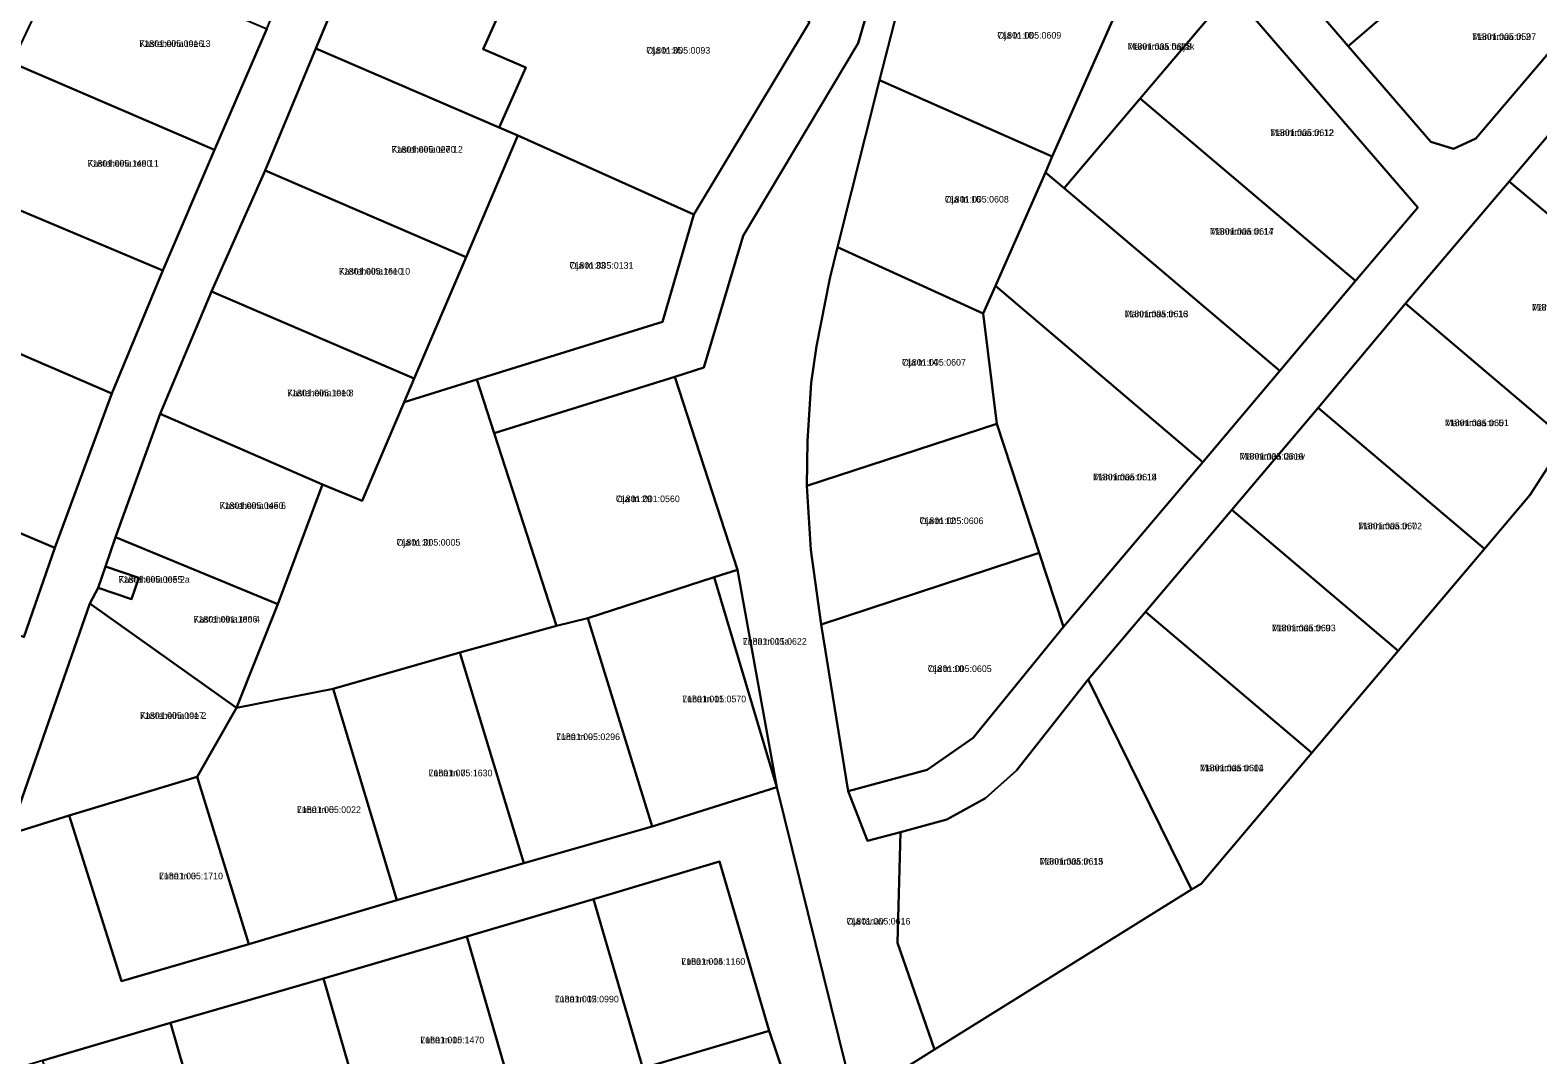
# Model space of a CAD drawing. Extents: x 529768 to 552006, y 6562269 to 6580975.
# Drawn here: x 536849.5 to 537191.7, y 6574124 to 6574356.4 of the extents above; entities that cross this region are included whole.
import ezdxf

# ---------------------------------------------------------------- set-up
doc = ezdxf.new("R2010")
doc.units = 0
for name, color, linetype in [('L_AADRESS', 7, 'Continuous'), ('PIIR', 7, 'Continuous'), ('TUNNUS', 7, 'Continuous')]:
    doc.layers.add(name, color=color, linetype=linetype)

msp = doc.modelspace()

# ---------------------------------------------------------------- linework, layer by layer
at = {"layer": 'PIIR'}
for points in [[(536848.11, 6574218.76), (536855.09, 6574238.97), (536868.03, 6574273.98), (536879.6, 6574301.9), (536891.37, 6574329.26), (536903.26, 6574356.78), (536914.89, 6574384.31), (536926.66, 6574411.99), (536938.46, 6574439.65), (536950.24, 6574467.12), (536913.03, 6574482.78), (536876.66, 6574498.44), (536839.93, 6574514.2)], [(537058.85, 6574426.74), (537037.46, 6574353.46), (537011.36, 6574309.79), (537002.42, 6574279.87), (536995.85, 6574277.77), (536954.81, 6574265.02), (536950.86, 6574277.19), (536993.03, 6574290.28), (537000.17, 6574314.62), (537026.37, 6574358.24)], [(537051.59, 6574381.3), (537042.29, 6574345.06), (537032.75, 6574307.23), (537030.98, 6574300.09), (537027.97, 6574284.72), (537026.74, 6574276.42), (537025.95, 6574263.3), (537025.82, 6574253.03), (537026.7, 6574238.56), (537029.01, 6574221.62), (537035.19, 6574183.8), (537039.58, 6574172.51), (537047.04, 6574174.52), (537046.35, 6574149.38), (537054.78, 6574125.16), (537036.51, 6574113.77), (537018.95, 6574184.72), (537010.08, 6574234.01), (536995.85, 6574277.77), (537002.42, 6574279.87), (537011.36, 6574309.79), (537037.46, 6574353.46), (537058.85, 6574426.74)], [(536925.81, 6574379.67), (536914.39, 6574352.3), (536902.87, 6574324.61), (536890.71, 6574297.13), (536879.02, 6574269.41), (536868.91, 6574241.43), (536866.6, 6574234.77), (536864.98, 6574229.95), (536863.06, 6574226.35), (536844.85, 6574174.03), (536858.39, 6574178.29), (536870.25, 6574140.65), (536899.17, 6574149.08), (536932.73, 6574159.05), (536961.59, 6574167.42), (536990.71, 6574175.75), (537018.95, 6574184.72), (537036.51, 6574113.77)], [(537128.66, 6574376.07), (537148.66, 6574352.81), (537167.43, 6574331.07), (537172.56, 6574329.53), (537177.64, 6574331.83), (537204.91, 6574363.99)], [(537212.84, 6574354.8), (537185.18, 6574322.09), (537161.63, 6574294.39), (537141.8, 6574270.76), (537122.23, 6574247.61), (537102.65, 6574224.46), (537089.61, 6574209.09), (537073.36, 6574188.47), (537066.32, 6574182.19), (537057.54, 6574177.35), (537047.04, 6574174.52), (537039.58, 6574172.51), (537035.19, 6574183.8), (537053.07, 6574188.61), (537063.54, 6574195.92), (537084.02, 6574221.05), (537115.69, 6574258.46), (537133.15, 6574279.15), (537150.3, 6574299.57), (537164.41, 6574316.2), (537122.1, 6574365.31)], [(537199.14, 6573885.6), (537082.16, 6574038.28), (537054.19, 6574078.17), (537036.51, 6574113.77), (537054.78, 6574125.16), (537113.11, 6574161.48), (537115.27, 6574162.8), (537140.4, 6574192.52), (537159.99, 6574215.66), (537179.58, 6574238.8), (537189.87, 6574250.96), (537198.07, 6574263.55)]]:
    msp.add_lwpolyline(points, dxfattribs=at)
for points in [[(537128.66, 6574376.07), (537166.46, 6574408.59), (537186.5, 6574385.35), (537148.66, 6574352.81)], [(537026.37, 6574358.24), (537000.17, 6574314.62), (536960.21, 6574332.56), (536955.96, 6574334.35), (536962, 6574347.99), (536952.35, 6574352.12), (536958.43, 6574365.86), (536963.07, 6574363.94), (536991.59, 6574384.37)], [(537105.74, 6574382.67), (537117.24, 6574370.49), (537111.74, 6574364.05), (537117.15, 6574359.47), (537101.43, 6574340.92), (537084.21, 6574320.56), (537079.92, 6574324.18), (537081.47, 6574327.75), (537096.34, 6574361.32)], [(537148.66, 6574352.81), (537186.5, 6574385.35), (537204.91, 6574363.99), (537177.64, 6574331.83), (537172.56, 6574329.53), (537167.43, 6574331.07)], [(536925.81, 6574379.67), (536958.43, 6574365.86), (536952.35, 6574352.12), (536962, 6574347.99), (536955.96, 6574334.35), (536914.39, 6574352.3)], [(537051.59, 6574381.3), (537096.34, 6574361.32), (537081.47, 6574327.75), (537042.29, 6574345.06)], [(536903.26, 6574356.78), (536891.37, 6574329.26), (536845.45, 6574349.03), (536858.12, 6574376.04)], [(537122.1, 6574365.31), (537164.41, 6574316.2), (537150.3, 6574299.57), (537101.43, 6574340.92), (537117.15, 6574359.47)], [(536948.45, 6574304.96), (536902.87, 6574324.61), (536914.39, 6574352.3), (536955.96, 6574334.35), (536960.21, 6574332.56)], [(537212.84, 6574354.8), (537238.29, 6574325.29), (537218.17, 6574294.4), (537185.18, 6574322.09)], [(536833.59, 6574321.31), (536845.45, 6574349.03), (536891.37, 6574329.26), (536879.6, 6574301.9)], [(537042.29, 6574345.06), (537081.47, 6574327.75), (537079.92, 6574324.18), (537068.59, 6574298.43), (537065.82, 6574292.19), (537032.75, 6574307.23)], [(536793.95, 6574337.96), (536833.59, 6574321.31), (536879.6, 6574301.9), (536868.03, 6574273.98), (536822.06, 6574293.79), (536814.06, 6574297.24), (536798.2, 6574304.12)], [(537101.43, 6574340.92), (537150.3, 6574299.57), (537133.15, 6574279.15), (537084.21, 6574320.56)], [(536936.7, 6574277.38), (536948.45, 6574304.96), (536960.21, 6574332.56), (537000.17, 6574314.62), (536993.03, 6574290.28), (536950.86, 6574277.19), (536934.43, 6574272.06)], [(536902.87, 6574324.61), (536948.45, 6574304.96), (536936.7, 6574277.38), (536890.71, 6574297.13)], [(537079.92, 6574324.18), (537084.21, 6574320.56), (537133.15, 6574279.15), (537115.69, 6574258.46), (537068.59, 6574298.43)], [(537185.18, 6574322.09), (537218.17, 6574294.4), (537198.07, 6574263.55), (537161.63, 6574294.39)], [(537032.75, 6574307.23), (537065.82, 6574292.19), (537068.94, 6574267.13), (537025.82, 6574253.03), (537025.95, 6574263.3), (537026.74, 6574276.42), (537027.97, 6574284.72), (537030.98, 6574300.09)], [(536789.89, 6574266.65), (536790.31, 6574302.7), (536798.2, 6574304.12), (536814.06, 6574297.24), (536822.06, 6574293.79), (536868.03, 6574273.98), (536855.09, 6574238.97), (536800.97, 6574261.89)], [(536936.7, 6574277.38), (536934.43, 6574272.06), (536928.31, 6574257.65), (536924.91, 6574249.64), (536915.9, 6574253.37), (536879.02, 6574269.41), (536890.71, 6574297.13)], [(537068.59, 6574298.43), (537115.69, 6574258.46), (537084.02, 6574221.05), (537078.53, 6574237.84), (537068.94, 6574267.13), (537065.82, 6574292.19)], [(537161.63, 6574294.39), (537198.07, 6574263.55), (537189.87, 6574250.96), (537179.58, 6574238.8), (537141.8, 6574270.76)], [(536896.38, 6574202.67), (536905.72, 6574226.24), (536915.9, 6574253.37), (536924.91, 6574249.64), (536928.31, 6574257.65), (536934.43, 6574272.06), (536950.86, 6574277.19), (536954.81, 6574265.02), (536968.94, 6574221.27), (536947.06, 6574215.22), (536918.3, 6574206.98)], [(536968.94, 6574221.27), (536954.81, 6574265.02), (536995.85, 6574277.77), (537010.08, 6574234.01), (537004.74, 6574232.31), (536976.09, 6574223.06)], [(536868.91, 6574241.43), (536879.02, 6574269.41), (536915.9, 6574253.37), (536905.72, 6574226.24)], [(537141.8, 6574270.76), (537179.58, 6574238.8), (537159.99, 6574215.66), (537122.23, 6574247.61)], [(536789.84, 6574260.87), (536789.89, 6574266.65), (536800.97, 6574261.89), (536855.09, 6574238.97), (536848.11, 6574218.76), (536810.37, 6574232.46), (536796.96, 6574235.46)], [(537025.82, 6574253.03), (537068.94, 6574267.13), (537078.53, 6574237.84), (537029.01, 6574221.62), (537026.7, 6574238.56)], [(537122.23, 6574247.61), (537159.99, 6574215.66), (537140.4, 6574192.52), (537102.65, 6574224.46)], [(536905.72, 6574226.24), (536896.38, 6574202.67), (536863.06, 6574226.35), (536864.98, 6574229.95), (536872.55, 6574227.37), (536874.19, 6574232.19), (536866.6, 6574234.77), (536868.91, 6574241.43)], [(537029.01, 6574221.62), (537078.53, 6574237.84), (537084.02, 6574221.05), (537063.54, 6574195.92), (537053.07, 6574188.61), (537035.19, 6574183.8)], [(536874.19, 6574232.19), (536872.55, 6574227.37), (536864.98, 6574229.95), (536866.6, 6574234.77)], [(536990.71, 6574175.75), (536976.09, 6574223.06), (537004.74, 6574232.31), (537018.95, 6574184.72)], [(537004.74, 6574232.31), (537010.08, 6574234.01), (537018.95, 6574184.72)], [(536896.38, 6574202.67), (536887.45, 6574187.06), (536858.39, 6574178.29), (536844.85, 6574174.03), (536863.06, 6574226.35)], [(536961.59, 6574167.42), (536947.06, 6574215.22), (536968.94, 6574221.27), (536976.09, 6574223.06), (536990.71, 6574175.75)], [(537102.65, 6574224.46), (537140.4, 6574192.52), (537115.27, 6574162.8), (537113.11, 6574161.48), (537089.61, 6574209.09)], [(536918.3, 6574206.98), (536947.06, 6574215.22), (536961.59, 6574167.42), (536932.73, 6574159.05)], [(537047.04, 6574174.52), (537057.54, 6574177.35), (537066.32, 6574182.19), (537073.36, 6574188.47), (537089.61, 6574209.09), (537113.11, 6574161.48), (537054.78, 6574125.16), (537046.35, 6574149.38)], [(536896.38, 6574202.67), (536918.3, 6574206.98), (536932.73, 6574159.05), (536899.17, 6574149.08), (536887.45, 6574187.06)], [(536887.45, 6574187.06), (536899.17, 6574149.08), (536870.25, 6574140.65), (536858.39, 6574178.29)], [(536794.93, 6574105.89), (536806.09, 6574067.53), (536817.38, 6574028.74), (536845.81, 6574036.87), (536874.93, 6574045.38), (536907.55, 6574054.92), (536938.29, 6574063.68), (536968.85, 6574072.27), (536999.32, 6574081.08), (537030.54, 6574090.1), (537017.23, 6574129.42), (537006, 6574167.84), (536977.4, 6574159.28), (536948.64, 6574150.84), (536916.08, 6574141.28), (536881.35, 6574131.19), (536852.44, 6574122.65), (536823.73, 6574114.17)], [(537006, 6574167.84), (537017.23, 6574129.42), (536988.57, 6574120.96), (536977.4, 6574159.28)], [(536977.4, 6574159.28), (536988.57, 6574120.96), (536959.72, 6574112.39), (536948.64, 6574150.84)], [(536916.08, 6574141.28), (536948.64, 6574150.84), (536959.72, 6574112.39), (536960.06, 6574111.22), (536957.76, 6574110.62), (536927.3, 6574102.56)], [(536892.53, 6574092.6), (536881.35, 6574131.19), (536916.08, 6574141.28), (536927.3, 6574102.56), (536896.17, 6574093.65)], [(536863.64, 6574084.33), (536852.44, 6574122.65), (536881.35, 6574131.19), (536892.53, 6574092.6)], [(536999.32, 6574081.08), (536988.57, 6574120.96), (537017.23, 6574129.42), (537030.54, 6574090.1)]]:
    msp.add_lwpolyline(points, close=True, dxfattribs=at)

# ---------------------------------------------------------------- texts
at = {"layer": 'L_AADRESS'}
for s, p in [('Oja tn 18', (537069.02, 6574354.53)), ('Männimaa tn 2', (537176.78, 6574354.22)), ('Kasteheina tee 13', (536874.31, 6574352.65)), ('Oja tn 35', (536989.36, 6574351.12)), ('Männimaa haljak', (537098.58, 6574351.98)), ('Männimaa tn 12', (537130.94, 6574332.44)), ('Kasteheina tee 12', (536931.54, 6574328.63)), ('Kasteheina tee 11', (536862.55, 6574325.46)), ('Oja tn 16', (537057.11, 6574317.33)), ('Männimaa tn 14', (537117.29, 6574310.04)), ('Oja tn 33', (536971.94, 6574302.31)), ('Kasteheina tee 10', (536919.59, 6574300.99)), ('Männimaa tn 3', (537190.31, 6574292.82)), ('Männimaa tn 16', (537097.87, 6574291.32)), ('Oja tn 14', (537047.38, 6574280.33)), ('Kasteheina tee 8', (536907.85, 6574273.38)), ('Männimaa tn 5', (537170.6, 6574266.6)), ('Männimaa tänav', (537124.02, 6574259.02)), ('Männimaa tn 18', (537090.75, 6574254.31)), ('Kasteheina tee 6', (536892.52, 6574247.82)), ('Oja tn 29', (536982.45, 6574249.36)), ('Oja tn 12', (537051.37, 6574244.38)), ('Männimaa tn 7', (537150.9, 6574243.21)), ('Oja tn 31', (536932.66, 6574239.49)), ('Kasteheina tee 2a', (536869.58, 6574231.07)), ('Kasteheina tee 4', (536886.59, 6574222.05)), ('Männimaa tn 9', (537131.31, 6574220.07)), ('Luha tn 11a', (537011.26, 6574217.01)), ('Oja tn 10', (537053.23, 6574210.82)), ('Luha tn 11', (536997.52, 6574203.95)), ('Kasteheina tee 2', (536874.46, 6574200.19)), ('Luha tn 9', (536968.89, 6574195.38)), ('Luha tn 7', (536939.95, 6574187.16)), ('Männimaa tn 11', (537115, 6574188.32)), ('Luha tn 5', (536910.09, 6574178.84)), ('Männimaa tn 13', (537078.58, 6574167.12)), ('Luha tn 3', (536878.78, 6574163.79)), ('Oja tänav', (537034.78, 6574153.53)), ('Luha tn 14', (536997.31, 6574144.39)), ('Luha tn 12', (536968.61, 6574135.86)), ('Luha tn 10', (536938.07, 6574126.57))]:
    msp.add_text(s, height=1.5, dxfattribs=at).set_placement(p)
at = {"layer": 'TUNNUS'}
for s, p in [('71801:005:0609', (537069.02, 6574354.53)), ('71801:005:0597', (537176.78, 6574354.22)), ('71801:005:0016', (536874.31, 6574352.65)), ('71801:005:0093', (536989.36, 6574351.12)), ('71801:005:0618', (537098.58, 6574351.98)), ('71801:005:0612', (537130.94, 6574332.44)), ('71801:005:0270', (536931.54, 6574328.63)), ('71801:005:1490', (536862.55, 6574325.46)), ('71801:005:0608', (537057.11, 6574317.33)), ('71801:005:0617', (537117.29, 6574310.04)), ('71801:005:0131', (536971.94, 6574302.31)), ('71801:005:1610', (536919.59, 6574300.99)), ('71801:005:0599', (537190.31, 6574292.82)), ('71801:005:0613', (537097.87, 6574291.32)), ('71801:005:0607', (537047.38, 6574280.33)), ('71801:005:1010', (536907.85, 6574273.38)), ('71801:005:0601', (537170.6, 6574266.6)), ('71801:005:0619', (537124.02, 6574259.02)), ('71801:005:0614', (537090.75, 6574254.31)), ('71801:005:0450', (536892.52, 6574247.82)), ('71801:001:0560', (536982.45, 6574249.36)), ('71801:005:0606', (537051.37, 6574244.38)), ('71801:005:0602', (537150.9, 6574243.21)), ('71801:005:0005', (536932.66, 6574239.49)), ('71801:005:0055', (536869.58, 6574231.07)), ('71801:001:1806', (536886.59, 6574222.05)), ('71801:005:0603', (537131.31, 6574220.07)), ('71801:005:0622', (537011.26, 6574217.01)), ('71801:005:0605', (537053.23, 6574210.82)), ('71801:005:0570', (536997.52, 6574203.95)), ('71801:005:0017', (536874.46, 6574200.19)), ('71801:005:0296', (536968.89, 6574195.38)), ('71801:005:1630', (536939.95, 6574187.16)), ('71801:005:0604', (537115, 6574188.32)), ('71801:005:0022', (536910.09, 6574178.84)), ('71801:005:0615', (537078.58, 6574167.12)), ('71801:005:1710', (536878.78, 6574163.79)), ('71801:005:0616', (537034.78, 6574153.53)), ('71801:005:1160', (536997.31, 6574144.39)), ('71801:005:0990', (536968.61, 6574135.86)), ('71801:005:1470', (536938.07, 6574126.57))]:
    msp.add_text(s, height=1.5, dxfattribs=at).set_placement(p)

doc.saveas('drawing.dxf')
